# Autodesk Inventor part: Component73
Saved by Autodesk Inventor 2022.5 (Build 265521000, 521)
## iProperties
Created: 2024-12
Part Number: Component73
Material: Generic
Document SubType Name: Modeling
Designer: AdminForWorker
Density: 1 g/cm^3
Appearance: Default
Title: Component73
Author: AdminForWorker
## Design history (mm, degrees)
feature "Body1"
body "Solid1"
